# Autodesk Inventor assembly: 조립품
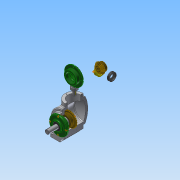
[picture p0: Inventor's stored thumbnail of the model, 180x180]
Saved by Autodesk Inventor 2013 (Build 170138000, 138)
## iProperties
Created: 2017-04
Part Number: 조립품
Document SubType Name: Assembly
Designer: MR
Author: MR
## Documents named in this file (14)
- C:\Users\MR\Desktop\470408V1003\답안조립품.iam
- C:\Users\MR\Desktop\470408V1003\본체.ipt
- C:\Users\MR\Desktop\470408V1003\메인 베벨기어.ipt
- C:\Users\MR\Desktop\470408V1003\메인 축.ipt
- 메인 축.ipt
- C:\Users\MR\Desktop\470408V1003\키 5x5.ipt
- C:\Users\MR\Desktop\470408V1003\베어링 6203.ipt
- C:\Users\MR\Desktop\470408V1003\볼트 M4.ipt
- C:\Users\MR\Desktop\470408V1003\오일실 17 32 8.ipt
- C:\Users\MR\Desktop\470408V1003\커버.ipt
- C:\Users\MR\Desktop\470408V1003\서브 베벨기어.ipt
- C:\Users\MR\Desktop\470408V1003\서브 축.ipt
- 서브 축.ipt
- C:\Users\MR\Desktop\470408V1003\키 4x4.ipt
